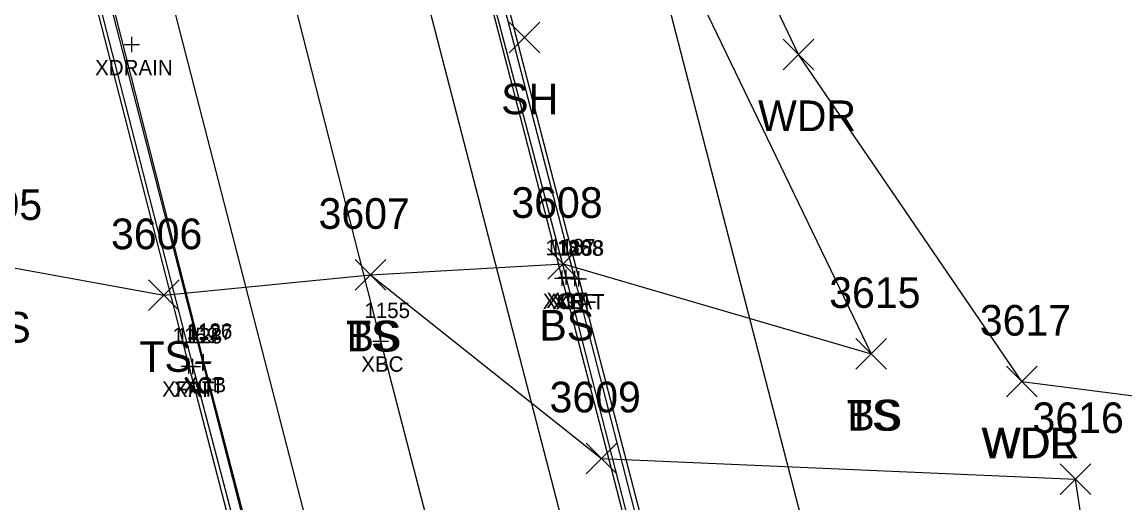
# Model space of a CAD drawing. Extents: x 1601151 to 1602912, y 499508 to 501770.
# Drawn here: x 1601528 to 1601599.8, y 500794 to 500825.3 of the extents above; entities that cross this region are included whole.
import ezdxf

# ---------------------------------------------------------------- set-up
doc = ezdxf.new("R2010")
doc.units = 0
for name, color, linetype in [('B_A', 7, 'Continuous'), ('B_I', 7, 'Continuous'), ('B_TIC', 7, 'Continuous'), ('BB', 7, 'Continuous'), ('BDC', 7, 'Continuous'), ('BELB', 7, 'Continuous'), ('BF', 7, 'Continuous'), ('BR', 7, 'Continuous'), ('L_A', 7, 'Continuous'), ('L_I', 7, 'Continuous'), ('L_TIC', 7, 'Continuous'), ('LAWA', 7, 'Continuous'), ('LELB', 7, 'Continuous'), ('UCO', 7, 'Continuous')]:
    doc.layers.add(name, color=color, linetype=linetype)

msp = doc.modelspace()

# ---------------------------------------------------------------- linework, layer by layer
at = {"layer": 'B_TIC'}
for p, q in [((1601535.109, 500823.862), (1601535.185, 500823.862)), ((1601563.16, 500808.618), (1601563.236, 500808.618)), ((1601563.411, 500808.684), (1601563.487, 500808.684)), ((1601563.979, 500808.593), (1601564.055, 500808.593)), ((1601564.253, 500808.582), (1601564.329, 500808.582)), ((1601551.33, 500804.521), (1601551.406, 500804.521)), ((1601539.745, 500803.087), (1601539.821, 500803.087)), ((1601539.776, 500803.176), (1601539.852, 500803.176)), ((1601538.828, 500802.891), (1601538.904, 500802.891)), ((1601539.087, 500802.864), (1601539.163, 500802.864))]:
    msp.add_line(p, q, dxfattribs=at)
for points in [[(1601534.606, 500823.862), (1601535.606, 500823.862)], [(1601535.106, 500823.362), (1601535.106, 500824.362)], [(1601563.157, 500808.118), (1601563.157, 500809.118)], [(1601563.408, 500808.184), (1601563.408, 500809.184)], [(1601563.976, 500808.093), (1601563.976, 500809.093)], [(1601564.25, 500808.082), (1601564.25, 500809.082)], [(1601562.657, 500808.618), (1601563.657, 500808.618)], [(1601562.908, 500808.684), (1601563.908, 500808.684)], [(1601563.476, 500808.593), (1601564.476, 500808.593)], [(1601563.75, 500808.582), (1601564.75, 500808.582)], [(1601550.827, 500804.521), (1601551.827, 500804.521)], [(1601551.327, 500804.021), (1601551.327, 500805.021)], [(1601539.773, 500802.676), (1601539.773, 500803.676)], [(1601538.825, 500802.391), (1601538.825, 500803.391)], [(1601539.084, 500802.364), (1601539.084, 500803.364)], [(1601539.242, 500803.087), (1601540.242, 500803.087)], [(1601539.273, 500803.176), (1601540.273, 500803.176)], [(1601539.742, 500802.587), (1601539.742, 500803.587)], [(1601538.325, 500802.891), (1601539.325, 500802.891)], [(1601538.584, 500802.864), (1601539.584, 500802.864)]]:
    msp.add_lwpolyline(points, dxfattribs=at)
at = {"layer": 'BB'}
for points in [[(1601612.43, 500602.27), (1601552.33, 500834.638)], [(1601596.605, 500598.195), (1601536.682, 500830.877)]]:
    msp.add_lwpolyline(points, dxfattribs=at)
at = {"layer": 'BDC'}
for points in [[(1601626.62, 500562.484), (1601618.762, 500592.927), (1601608.069, 500634.25), (1601598.914, 500669.817), (1601586.174, 500719.227), (1601573.535, 500768.43), (1601563.157, 500808.618), (1601554.18, 500843.361), (1601545.696, 500876.636)], [(1601627.365, 500562.647), (1601626.817, 500562.743), (1601626.575, 500563.06), (1601618.94, 500592.981), (1601608.354, 500634.47), (1601599.142, 500669.932), (1601586.408, 500719.217), (1601573.699, 500768.593), (1601563.408, 500808.684), (1601554.3, 500843.382), (1601545.843, 500876.671)], [(1601521.711, 500869.959), (1601522.401, 500870.191), (1601530.668, 500838.288), (1601539.742, 500803.087), (1601549.8, 500763.941), (1601562.902, 500713.198), (1601575.298, 500665.088), (1601584.682, 500628.799), (1601595.241, 500588.098), (1601603.293, 500556.622), (1601602.827, 500556.326)], [(1601522.54, 500870.251), (1601530.887, 500838.161), (1601539.773, 500803.176), (1601550.059, 500763.65), (1601563.09, 500713.388), (1601575.504, 500665.097), (1601584.832, 500628.831), (1601595.285, 500588.334), (1601603.432, 500556.591), (1601602.763, 500556.075)]]:
    msp.add_lwpolyline(points, dxfattribs=at)
at = {"layer": 'BELB'}
msp.add_lwpolyline([(1601614.122, 500560.679), (1601606.109, 500592.04), (1601595.825, 500632.34), (1601585.652, 500672.123), (1601574.355, 500716.245), (1601561.498, 500765.241), (1601551.327, 500804.521), (1601542.34, 500839.856), (1601533.48, 500873.114)], dxfattribs=at)
at = {"layer": 'BF'}
for points in [[(1601546.596, 500876.467), (1601555.117, 500843.825), (1601564.25, 500808.582), (1601574.552, 500768.924), (1601587.26, 500719.439), (1601599.8, 500670.488), (1601609.07, 500634.571), (1601619.784, 500593.212)], [(1601521.711, 500869.959), (1601529.926, 500837.537), (1601538.825, 500802.891), (1601549.015, 500763.542), (1601561.986, 500712.939), (1601574.422, 500664.924), (1601583.827, 500628.557), (1601594.342, 500587.938), (1601602.827, 500556.326)]]:
    msp.add_lwpolyline(points, dxfattribs=at)
at = {"layer": 'BR'}
for points in [[(1601626.891, 500563.91), (1601619.486, 500592.933), (1601608.823, 500634.178), (1601599.631, 500670.204), (1601586.939, 500719.228), (1601574.289, 500768.594), (1601563.976, 500808.593), (1601554.991, 500843.345), (1601546.615, 500875.695)], [(1601521.915, 500869.371), (1601530.025, 500838.058), (1601539.084, 500802.864), (1601549.326, 500763.869), (1601562.422, 500713.041), (1601574.564, 500665.146), (1601584.098, 500628.637), (1601594.598, 500587.839), (1601602.424, 500557.542)]]:
    msp.add_lwpolyline(points, dxfattribs=at)
at = {"layer": 'L_TIC'}
for points in [[(1601559.694, 500823.319), (1601561.694, 500825.319)], [(1601561.694, 500823.319), (1601559.694, 500825.319)], [(1601577.563, 500822.216), (1601579.563, 500824.216)], [(1601579.563, 500822.216), (1601577.563, 500824.216)], [(1601562.231, 500808.556), (1601564.231, 500810.556)], [(1601564.231, 500808.556), (1601562.231, 500810.556)], [(1601549.664, 500807.842), (1601551.664, 500809.842)], [(1601551.664, 500807.842), (1601549.664, 500809.842)], [(1601549.664, 500807.842), (1601551.664, 500809.842)], [(1601551.664, 500807.842), (1601549.664, 500809.842)], [(1601536.193, 500806.513), (1601538.193, 500808.513)], [(1601538.193, 500806.513), (1601536.193, 500808.513)], [(1601582.302, 500802.684), (1601584.302, 500804.684)], [(1601584.302, 500802.684), (1601582.302, 500804.684)], [(1601582.302, 500802.684), (1601584.302, 500804.684)], [(1601584.302, 500802.684), (1601582.302, 500804.684)], [(1601592.118, 500800.876), (1601594.118, 500802.876)], [(1601594.118, 500800.876), (1601592.118, 500802.876)], [(1601592.118, 500800.876), (1601594.118, 500802.876)], [(1601594.118, 500800.876), (1601592.118, 500802.876)], [(1601564.727, 500795.869), (1601566.727, 500797.869)], [(1601566.727, 500795.869), (1601564.727, 500797.869)], [(1601595.607, 500794.518), (1601597.607, 500796.518)], [(1601597.607, 500794.518), (1601595.607, 500796.518)], [(1601595.607, 500794.518), (1601597.607, 500796.518)], [(1601597.607, 500794.518), (1601595.607, 500796.518)]]:
    msp.add_lwpolyline(points, dxfattribs=at)
at = {"layer": 'LAWA'}
for points in [[(1601593.118, 500801.876), (1601578.563, 500823.216), (1601571.541, 500837.943), (1601571.618, 500859.309), (1601565.589, 500876.721), (1601544.544, 500946.966)], [(1601593.118, 500801.876), (1601615.826, 500798.979), (1601635.321, 500780.926), (1601655.205, 500765.076), (1601678.727, 500755.008), (1601678.275, 500744.945), (1601691.757, 500735.443), (1601706.12, 500726.411), (1601725.157, 500712.057), (1601744.248, 500704.198), (1601769.856, 500702.951), (1601803.71, 500682.949)]]:
    msp.add_lwpolyline(points, dxfattribs=at)
at = {"layer": 'LELB'}
for points in [[(1601551.195, 500842.188), (1601558.941, 500840.906), (1601569.418, 500832.523), (1601583.302, 500803.684)], [(1601317.459, 500821.176), (1601360.868, 500819.599), (1601396.073, 500815.793), (1601437.388, 500810.521), (1601491.797, 500811.5), (1601526.696, 500809.421), (1601537.193, 500807.513), (1601550.664, 500808.842), (1601565.727, 500796.869), (1601596.607, 500795.518)], [(1601550.664, 500808.842), (1601563.231, 500809.556), (1601583.302, 500803.684)], [(1601597.777, 500761.537), (1601600.579, 500768.923), (1601596.607, 500795.518)]]:
    msp.add_lwpolyline(points, dxfattribs=at)
at = {"layer": 'UCO'}
msp.add_lwpolyline([(1601636.552, 500569.306), (1601558.395, 500871.752)], dxfattribs=at)

# ---------------------------------------------------------------- texts
at = {"layer": 'B_A'}
for s, p in [('XDRAIN', (1601532.716, 500821.862)), ('XCB', (1601561.893, 500806.618)), ('XCT', (1601562.128, 500806.684)), ('XFAT', (1601562.506, 500806.582)), ('XRF', (1601562.736, 500806.593)), ('XBC', (1601550.063, 500802.521)), ('XFAT', (1601537.081, 500800.891)), ('XRF', (1601537.844, 500800.864)), ('XCT', (1601538.462, 500801.087)), ('XCB', (1601538.509, 500801.176))]:
    msp.add_text(s, height=1, dxfattribs=at).set_placement(p)
at = {"layer": 'B_I'}
for s, p in [('1186', (1601562.067, 500810.118)), ('1187', (1601562.345, 500810.184)), ('1208', (1601562.864, 500810.082)), ('1188', (1601562.913, 500810.093)), ('1155', (1601550.264, 500806.021)), ('1159', (1601537.758, 500804.391)), ('1128', (1601538.021, 500804.364)), ('1127', (1601538.679, 500804.587)), ('1126', (1601538.683, 500804.676))]:
    msp.add_text(s, height=1, dxfattribs=at).set_placement(p)
at = {"layer": 'L_A'}
for s, p in [('SH', (1601559.182, 500819.319)), ('WDR', (1601575.925, 500818.216)), ('BS', (1601561.672, 500804.556)), ('TS', (1601525.106, 500804.421)), ('TS', (1601549.074, 500803.842)), ('BS', (1601549.105, 500803.842)), ('TS', (1601535.603, 500802.513)), ('TS', (1601581.711, 500798.684)), ('BS', (1601581.743, 500798.684)), ('WDR', (1601590.48, 500796.876)), ('WDL', (1601590.535, 500796.876))]:
    msp.add_text(s, height=2, dxfattribs=at).set_placement(p)
at = {"layer": 'L_I'}
for s, p in [('3605', (1601523.31, 500812.421)), ('3608', (1601559.845, 500812.556)), ('3607', (1601547.279, 500811.842)), ('3607', (1601547.279, 500811.842)), ('3606', (1601533.752, 500810.513)), ('3615', (1601580.562, 500806.684)), ('3615', (1601580.562, 500806.684)), ('3617', (1601590.378, 500804.876)), ('3617', (1601590.378, 500804.876)), ('3609', (1601562.334, 500799.869)), ('3616', (1601593.812, 500798.518)), ('3616', (1601593.812, 500798.518))]:
    msp.add_text(s, height=2, dxfattribs=at).set_placement(p)

doc.saveas('drawing.dxf')
